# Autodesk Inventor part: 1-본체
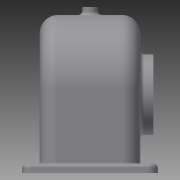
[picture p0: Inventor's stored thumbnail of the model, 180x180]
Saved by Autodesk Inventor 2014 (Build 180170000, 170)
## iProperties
Created: 2016-01
Part Number: 1-본체
Material: Generic
Document SubType Name: Modeling
Designer: KB20301
Density: 1 g/cm^3
Appearance: Default
Mass: 298.675 g
Surface Area: 1000.05 cm^2
Volume: 298.675 cm^3
Author: KB20301
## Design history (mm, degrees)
sketch "스케치1"
  geometry: L1 (-57, 0)-(-57, -57); L2 (-57, -57)-(57, -57); L3 (57, 0)-(57, -57); A1 r 57 centre (0, 0) between (57, 0) and (-57, 0); 1 further point
  constraints: 6 end point, 2 perpendicular, 2 point on circle, 2 tangent, 1 centre point, 1 coincident, 1 vertical
  dimensions: "d0" = 114 diameter of A1; "d1" = 57 distance from line of L2 point (0, 0)
extrude "돌출1" new body sketch "스케치1" stored distance "d2" = 77; taper "d3" = 0 deg
feature "쉘1" dims "d8" = 6, "d19" = 5
sketch "스케치3"
  geometry: L1 (108, -72)-(6, -72) reference; L2 (6, -72)-(6, -5) reference; L3 (6, -5)-(108, -5) reference; L4 (108, -5)-(108, -72) reference; L5 (127, 13.5)-(-13, 13.5); L6 (-13, 13.5)-(-13, -90.5); L7 (-13, -90.5)-(127, -90.5); L8 (127, -90.5)-(127, 13.5); L9 (127, 13.5)-(-13, -90.5); L10 (-13, 13.5)-(127, -90.5); 2 further points
  constraints: 12 end point, 2 midpoint, 2 parallel, 1 horizontal, 1 perpendicular
  dimensions: "d10" = 104 distance of L7.end L5.start; "d11" = 140 distance of L6.end L7.end
extrude "돌출3" join sketch "스케치3" distance "d12" = 7; taper "d13" = 0 deg
sketch "스케치4"
  geometry: L1 (70, -57)-(-70, -57) reference; L2 (70, -64)-(-70, -64) reference; C1 r 31 at (0, -4); A1 r 57 centre (0, 0) between (57, 0) and (-57, 0) reference
  constraints: 1 centre point, 1 vertical alignment
  dimensions: "d14" = 62 diameter of C1; "d16" = 60 distance from line of L2 C1.centre
extrude "돌출4" join sketch "스케치4" distance "d17" = 10; taper "d18" = 0 deg
sketch "스케치6"
  geometry: L1 (-4, -19.5)-(-4, -33.5); L2 (-64, 33.5)-(-64, -33.5) reference; L3 (0, -38.5)-(57, -38.5) reference; L4 (0, -33.5)-(51, -33.5) reference; L5 (-4, -19.5)-(24, -19.5); L6 (24, -19.5)-(35.747, -33.5); L7 (35.747, -33.5)-(-4, -33.5); 1 further point
  constraints: 8 end point, 1 parallel, 1 perpendicular, 1 vertical
  dimensions: "d20" = 60 distance between parallel lines of L2 L1; "d21" = 19 distance between parallel lines of L5 L3; "d22" = 14 distance between parallel lines of L5 L7; "d23" = 50 deg angle of L5 L6; "d24" = 56 diameter of L5.end L1
revolve "회전1" stored, may be unused: angle "d25" = 90 deg
sketch "스케치7"
  geometry: L1 (-4, -38.5)-(-4, -19.5); L2 (-64, 33.5)-(-64, -33.5) reference; L3 (0, -38.5)-(57, -38.5) reference; L4 (0, -38.5)-(-57, -38.5) reference; L5 (-4, -35.5)-(30.899, -35.5); L6 (-32, -19.5)-(24, -19.5) reference; L7 (-43.747, -33.5)-(35.747, -33.5) reference; L8 (24, -19.5)-(35.747, -33.5) reference; L9 (30.899, -35.5)-(33.416, -38.5); 1 further point
  constraints: 6 end point, 3 point on line, 2 parallel, 1 midpoint, 1 vertical
  dimensions: "d30" = 60 distance between parallel lines of L2 L1; "d31" = 3 distance between parallel lines of L5 L3; "d32" = 5 distance between parallel lines of L8 L9
revolve "회전2" sketch "스케치7" stored, may be unused: angle "d34" = 90 deg
sketch "스케치8"
  geometry: C1 r 34.899 at (0, 0) reference; C2 r 20 at (0, 0); A1 r 57 centre (0, 4) between (57, 4) and (-57, 4) reference
  constraints: 1 centre point, 1 coincident
  dimensions: "d36" = 40 diameter of C2
extrude "돌출5" cut sketch "스케치8" stored distance "d37" = 10; taper "d38" = 0 deg
sketch "스케치9"
  geometry: C1 r 31 at (0, 0) reference; C2 r 20 at (0, 0)
  constraints: 1 centre point, 1 coincident
  dimensions: "d39" = 40 diameter of C2
extrude "돌출6" cut sketch "스케치9" distance "d40" = 15; taper "d41" = 0 deg
node "작업 평면1"
sketch "스케치10"
  geometry: C1 r 6 at (-57, -38.5); 1 further point
  constraints: 1 centre point, 1 coincident
  dimensions: "d43" = 12 diameter of C1
extrude "돌출7" join sketch "스케치10" stored distance "d44" = 15; taper "d45" = 0 deg
hole "구멍1" diameter "d48" = 4.459; stored, may be unused: countersink angle "d52" = 90 deg, drill point angle "d54" = 118 deg; dims "d46" = 10, "d47" = 10, "d49" = 6, "d50" = 4, "d51" = 2, "d53" = 8
sketch "스케치12" dims "d55" = 48
  geometry: C1 r 20 at (0, 0) reference; C2 r 31 at (0, 0) reference; 2 further points
  constraints: 2 vertical alignment, 1 coincident, 2 other
hole "구멍2" sketch "스케치12" at (0, 24) diameter "d56" = 2.459; stored, may be unused: countersink angle "d60" = 90 deg, drill point angle "d62" = 118 deg; dims "d57" = 6, "d58" = 4, "d59" = 2, "d61" = 8
sketch "스케치13" dims "d66" = 56
  geometry: C1 r 20 at (0, 0) reference; C2 r 34.899 at (0, 0) reference; 2 further points
  constraints: 2 vertical alignment, 1 coincident, 2 other
hole "구멍3" sketch "스케치13" at (0, 28) diameter "d67" = 2.459; stored, may be unused: countersink angle "d71" = 90 deg, drill point angle "d73" = 118 deg; dims "d68" = 7, "d69" = 4, "d70" = 2, "d72" = 9
sketch "스케치14"
  geometry: L1 (127, 90.5)-(127, -13.5) reference; L2 (-13, 90.5)-(127, 90.5) reference; C1 r 2.5 at (119, 82.5); 1 further point
  constraints: 1 centre point
  dimensions: "d77" = 8 distance from line of L1 C1.centre; "d78" = 8 distance from line of C1.centre L2; "d79" = 5 diameter of C1
extrude "돌출8" cut sketch "스케치14" stored distance "d80" = 15; taper "d81" = 0 deg
fillet "모깎기1" dims "d88" = 8
fillet "모깎기2" dims "d89" = 9
fillet "모깎기3" dims "d90" = 14
fillet "모깎기4" dims "d91" = 3
fillet "모깎기5" dims "d92" = 3
fillet "모깎기6" dims "d93" = 1
fillet "모깎기7" dims "d94" = 3
node "작업 평면2"
sketch "스케치15"
  geometry: L1 (64, 44)-(64, -44) reference; 2 further points
  constraints: 1 horizontal alignment, 1 other
  dimensions: "d96" = 30 distance from line of L1 point (34, 0)
feature "엠보싱1" sketch "스케치15" dims "d97" = 0.5, "d98" = 0
chamfer "모따기1" distance "d99" = 1; stored, may be unused: second distance "d100" = 2, angle "d101" = 45 deg
chamfer "모따기2" distance "d102" = 1; stored, may be unused: second distance "d103" = 2, angle "d104" = 45 deg
fillet "모깎기8" dims "d105" = 3
node "솔리드1"
pattern_circular "원형 패턴1" dims angle "d64" = 360 deg
pattern_circular "원형 패턴2" dims angle "d75" = 360 deg
pattern_linear "직사각형 패턴1" dims "d84" = 88
pattern_linear "직사각형 패턴2" dims "d87" = 124
node "투영된 루프1"
other parameters: "d42" = -127
